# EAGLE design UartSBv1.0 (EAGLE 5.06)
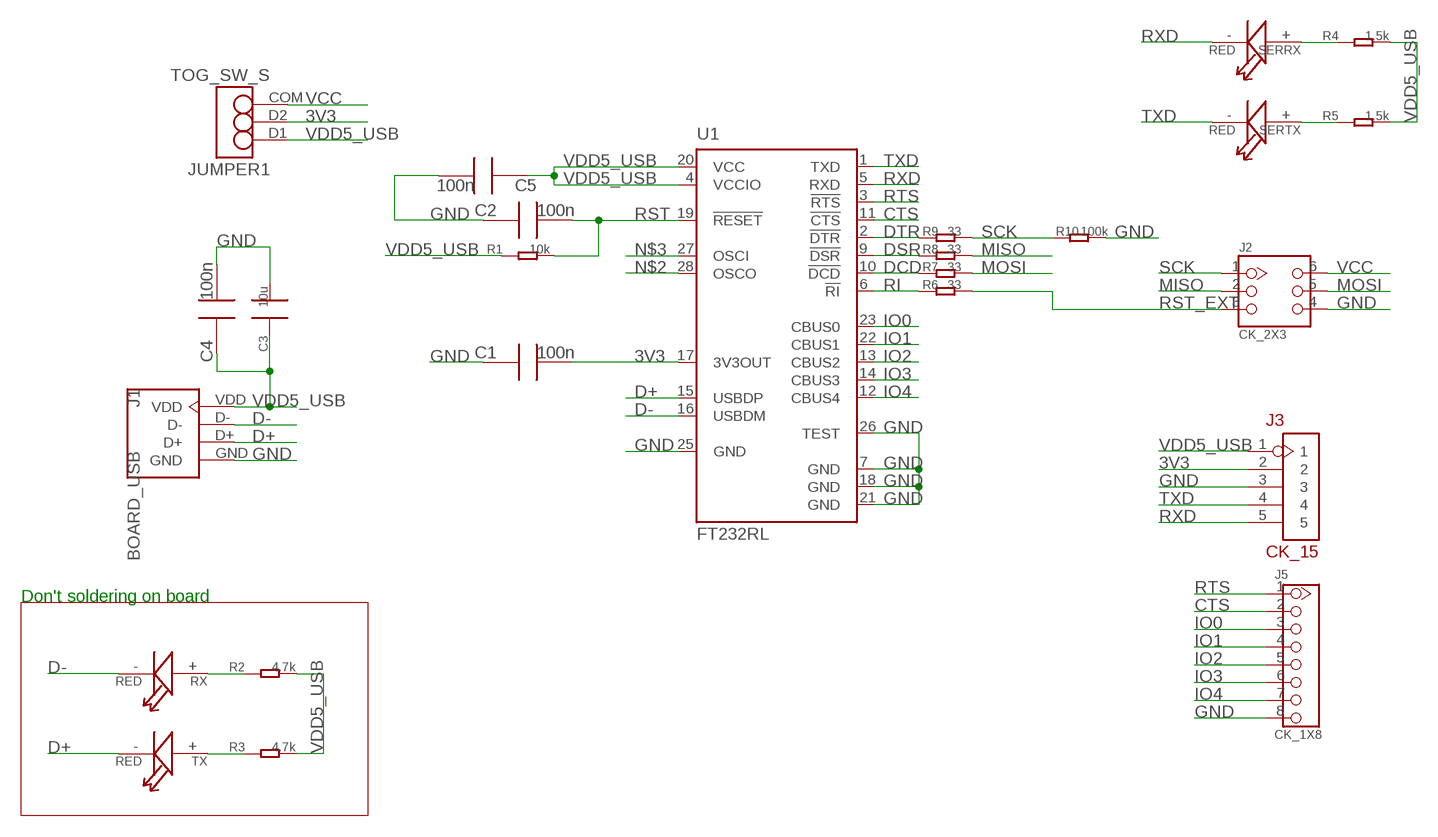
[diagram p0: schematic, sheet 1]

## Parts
C1  100n  C0603  [0603]
C2  100n  C0603  [0603]
C3  10u  C0805  [0805]
C4  100n  C0603  [0603]
C5  100n  C0603  [0603]
J1  BOARD_USB  [BOARD_USB]
J2  CK_2X3  [CK_2X3]
J3  CK_15  [CK_1*5]
J5  CK_1X8  [CK_1X8]
JUMPER1  TOG_SW_S  [TOG_SW_S]
R1  10k  R0603  [0603]
R2  4.7k  R0603  [0603]
R3  4.7k  R0603  [0603]
R4  1.5k  R0603  [0603]
R5  1.5k  R0603  [0603]
R6  33  R0603  [0603]
R7  33  R0603  [0603]
R8  33  R0603  [0603]
R9  33  R0603  [0603]
R10  100k  R0603  [0603]
RX  RED  LED0805  [LED0805]
SERRX  RED  LED0805  [LED0805]
SERTX  RED  LED0805  [LED0805]
TX  RED  LED0805  [LED0805]
U1  FT232RL  [SSOP28]

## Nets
3V3: C1.2 J3.2 JUMPER1.D2 U1.17(3V3OUT)
CTS: J5.2 U1.11(!CTS)
D+: J1.D+ TX.- U1.15(USBDP)
D-: J1.D- RX.- U1.16(USBDM)
DCD: R7.1 U1.10(!DCD)
DSR: R8.1 U1.9(!DSR)
DTR: R9.1 U1.2(!DTR)
GND: C1.1 C2.1 C3.2 C4.2 C5.2 J1.GND J2.4 J3.3 J5.8 R10.2 U1.7(GND) U1.18(GND) U1.21(GND) U1.25(GND) U1.26(TEST)
IO0: J5.3 U1.23(CBUS0)
IO1: J5.4 U1.22(CBUS1)
IO2: J5.5 U1.13(CBUS2)
IO3: J5.6 U1.14(CBUS3)
IO4: J5.7 U1.12(CBUS4)
MISO: J2.2 R8.2
MOSI: J2.5 R7.2
N$1: R4.1 SERRX.+
N$2: U1.28(OSCO)
N$3: U1.27(OSCI)
N$4: R5.1 SERTX.+
N$5: R2.1 RX.+
N$6: R3.1 TX.+
RI: R6.1 U1.6(!RI)
RST: C2.2 R1.2 U1.19(!RESET)
RST_EXT: J2.3 R6.2
RTS: J5.1 U1.3(!RTS)
RXD: J3.5 SERRX.- U1.5(RXD)
SCK: J2.1 R9.2 R10.1
TXD: J3.4 SERTX.- U1.1(TXD)
VCC: J2.6 JUMPER1.COM
VDD5_USB: C3.1 C4.1 C5.1 J1.VDD J3.1 JUMPER1.D1 R1.1 R2.2 R3.2 R4.2 R5.2 U1.4(VCCIO) U1.20(VCC)

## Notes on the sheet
- Don't soldering on board

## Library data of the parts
C1 C2 C4 C5 = CPT_SMD:C0603; C0603: 100N
C3 = CPT_SMD:C0805
J1 = CONNECTER:BOARD_USB
J2 = CONNECTER:CK_2X3
J3 = CONNECTER:CK_1*5
J5 = CONNECTER:CK_1X8
JUMPER1 = CPT_SMD:TOG_SW_S
R1-R10 = CPT_SMD:R0603
RX SERRX SERTX TX = CPT_SMD:LED0805
U1 = IC_SMD:FT232R: Source: http://www.ftdichip.com/Documents/DataSheets/DS_FT232R_v104.pdf

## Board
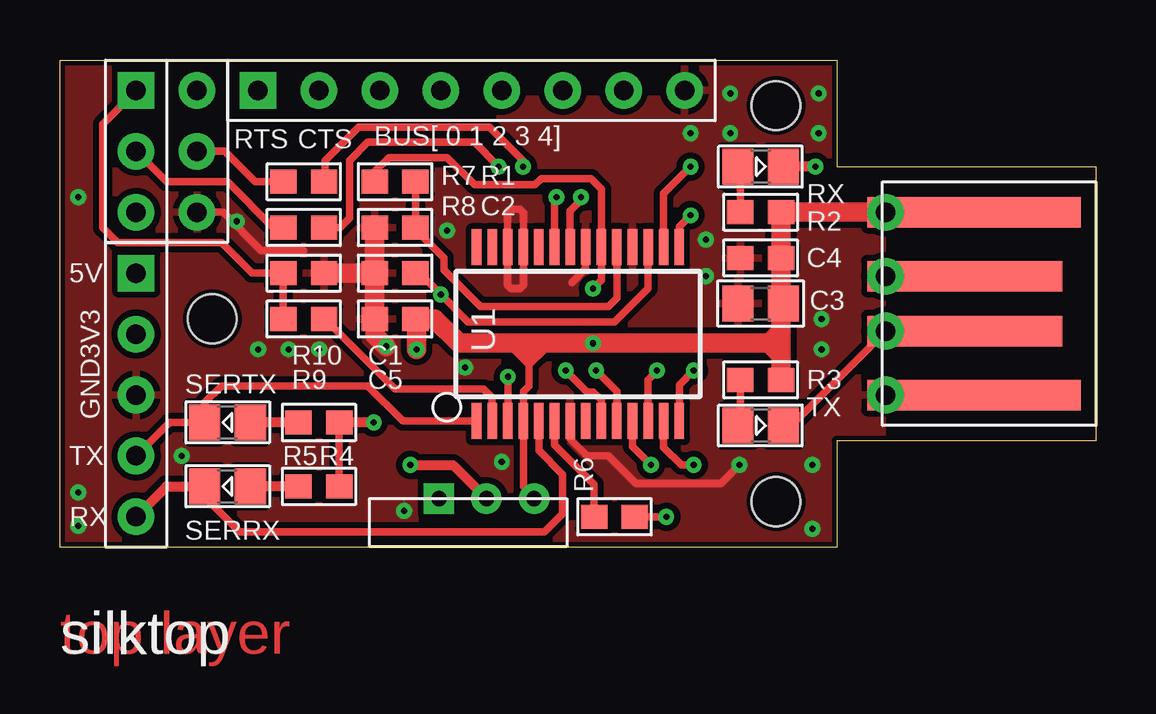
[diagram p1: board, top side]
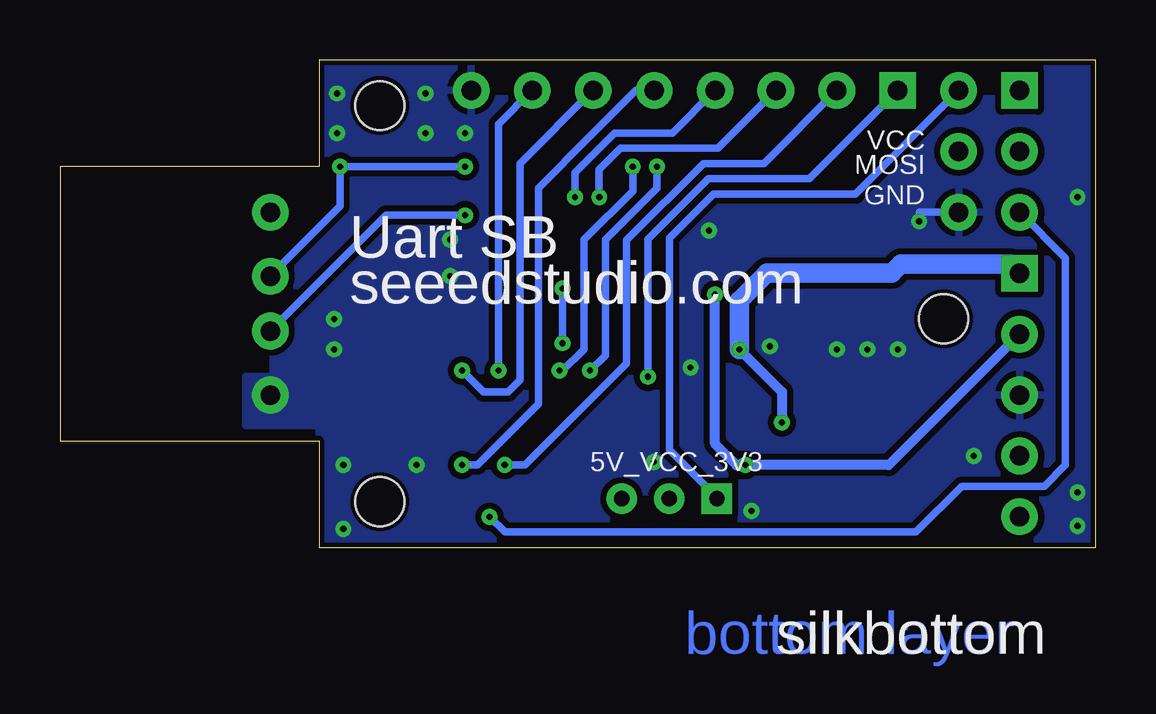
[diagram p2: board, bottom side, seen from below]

Size 43.18 x 20.32 mm. Coordinates in mm from the lower left corner, seen from the top.
Outline: 43.18,4.45 32.38,4.45 32.38,0 0,0 0,20.32 32.38,20.32 32.38,15.88 43.18,15.88 43.18,4.45
Copper layers (1*16): Top 0.035mm / dielectric 1.5mm / Bottom 0.035mm
Design rules "my rule": minimum track width 8mil, minimum drill 10mil, track to track 10mil, track to pad 6mil, pad to pad 6mil, via to via 10mil, smd to smd 6mil, copper to edge 5mil, drill to drill 10mil, minimum pad ring 10mil, minimum via ring 8mil, stop-mask expansion 3mil, vias tented up to drill 20mil, thermal gap 10mil
Holes 2.03 mm at 6.35,9.53 29.84,1.91 29.84,18.41
tRestrict: area 18.7,11.9 to 19.3,13; area 3.2,19.1 to 25.3,19.8; area 21,4.6 to 21.6,5.2
bRestrict: area 3.2,19.1 to 25.3,19.8

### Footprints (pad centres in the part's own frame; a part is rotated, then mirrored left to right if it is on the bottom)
0603 = smd 1.1 x 1: 1 -0.85,0; 2 0.85,0
0805 = smd 1.3 x 1.5: 1 -0.95,0; 2 0.95,0
BOARD_USB = smd 1.27 x 8.128: D+ 1.143,-0.381; D- -1.143,-0.381 | smd 1.27 x 8.89: GND 3.81,0; VDD -3.81,0
CK_2X3 = drill 0.813 pad 1.524 square: 1 -1.27,2.54 | drill 0.813 pad 1.524 round: 2 -1.27,0; 3 -1.27,-2.54; 4 1.27,-2.54; 5 1.27,0; 6 1.27,2.54
CK_1*5 = drill 0.813 pad 1.524 square: 1 0,5.08 | drill 0.813 pad 1.524 round: 2 0,2.54; 3 0,0; 4 0,-2.54; 5 0,-5.08
CK_1X8 = drill 0.813 pad 1.524 square: 1 0,8.89 | drill 0.813 pad 1.524 round: 2 0,6.35; 3 0,3.81; 4 0,1.27; 5 0,-1.27; 6 0,-3.81; 7 0,-6.35; 8 0,-8.89
TOG_SW_S = drill 0.635 pad 1.27 square: COM 0,-1.981 | drill 0.635 pad 1.27 round: D1 0,1.981; D2 0,0
LED0805 = smd 1.3 x 1.5: + -0.95,0; - 0.95,0
SSOP28 = smd 0.4 x 1.5: 1 -4.225,-3.625; 2 -3.575,-3.625; 3 -2.925,-3.625; 4 -2.275,-3.625; 5 -1.625,-3.625; 6 -0.975,-3.625; 7 -0.325,-3.625; 8 0.325,-3.625; 9 0.975,-3.625; 10 1.625,-3.625; 11 2.275,-3.625; 12 2.925,-3.625; 13 3.575,-3.625; 14 4.225,-3.625; 15 4.225,3.625; 16 3.575,3.625; 17 2.925,3.625; 18 2.275,3.625; 19 1.625,3.625; 20 0.975,3.625; 21 0.325,3.625; 22 -0.325,3.625; 23 -0.975,3.625; 24 -1.625,3.625; 25 -2.275,3.625; 26 -2.925,3.625; 27 -3.575,3.625; 28 -4.225,3.625

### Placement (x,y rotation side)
C1  13.97,11.43 0 top
C2  13.97,13.34 0 top
C3  29.21,10.16 180 top
C4  29.21,12.06 180 top
C5  13.97,9.53 180 top
J1  38.1,10.16 270 top
J2  4.45,16.51 0 top
J3  3.17,6.35 0 top
J5  17.14,19.05 90 top
JUMPER1  17.78,2.03 270 top
R1  13.97,15.24 0 top
R2  29.21,13.97 0 top
R3  29.21,6.99 0 top
R4  10.79,2.54 0 top
R5  10.79,5.21 0 top
R6  23.11,1.27 0 top
R7  10.16,15.24 180 top
R8  10.16,13.34 180 top
R9  10.16,9.53 180 top
R10  10.16,11.43 0 top
RX  29.21,15.88 0 top
SERRX  6.99,2.54 180 top
SERTX  6.99,5.21 180 top
TX  29.21,5.08 0 top
U1  21.59,8.89 0 top

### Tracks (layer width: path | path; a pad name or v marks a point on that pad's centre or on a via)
3V3  (via drill 0.25 pad 0.25)
  Top 0.305: C1.2 14.99,11.43 v15.88,10.54 17.02,9.4 23.11,9.4 24.52,10.8 U1.17
  Top 0.406: v14.61,3.43 16.38,3.43 JUMPER1.D2
  Bottom 0.406: v15.88,10.54 15.88,4.32 14.99,3.43 v14.61,3.43 8.64,3.43 J3.2
CTS  (via drill 0.25 pad 0.25)
  Top 0.305: U1.11 23.86,4.2 v24.64,3.43
  Bottom 0.305: J5.2 13.84,16 16.36,16 19.56,12.8 19.56,7.67 23.8,3.43 v24.64,3.43
D+  (via drill 0.25 pad 0.25, 0.81 pad 1.52)
  Top 0.305: U1.15 25.82,13.37 v26.29,13.84 | TX.- 30.48,5.08 v34.42,9.02
  Top 0.406: v34.42,9.02 J1.D+
  Bottom 0.305: v26.29,13.84 29.59,13.84 v34.42,9.02
D-  (via drill 0.25 pad 0.25, 0.81 pad 1.52)
  Top 0.305: U1.16 25.16,14.75 v26.29,15.88
  Top 0.406: v34.42,11.3 J1.D- | v31.5,15.88 RX.-
  Bottom 0.305: v26.29,15.88 v31.5,15.88 31.5,14.22 v34.42,11.3
DCD  (via drill 0.25 pad 0.25)
  Top 0.305: R7.1 11.05,15.24 11.05,16.13 12.45,17.53 17.91,17.53 19.3,16.13 v19.3,15.88 | U1.10 23.21,6.5 v22.35,7.37
  Bottom 0.305: v19.3,15.88 19.3,14.86 21.34,12.83 21.34,8.26 22.23,7.37 v22.35,7.37
DSR  (via drill 0.25 pad 0.25)
  Top 0.305: U1.9 22.57,6.14 22.23,6.48 21.97,6.48 v21.08,7.37 | R8.1 11.68,13.34 12.06,13.72 12.06,16.13 12.83,16.89 17.27,16.89 v18.29,15.88
  Bottom 0.305: v18.29,15.88 18.29,14.99 20.45,12.83 20.45,8 v21.08,7.37
DTR
  Top 0.305: 11.05,9.53 11.05,9.52 | U1.2 18.02,6.24 17.65,6.6 13.97,6.6 11.05,9.53 | R9.1 11.05,9.53
GND  (via drill 0.25 pad 0.25, 0.81 pad 1.52)
  Top 0.305: C2.1 13.08,13.34 13.12,13.3 | R10.2 11.01,11.53 | 10.16,12.38 8.38,12.38 6.79,13.97 J2.4 | U1.21 21.91,11.63 21.34,11.05 | U1.7 21.27,4.52 21.97,3.81 22.86,3.81 24,2.67 27.56,2.67 v28.32,3.43 | 19.32,10.93 U1.25 19.32,13.96 19.18,14.1 18.8,14.1 18.66,13.97 U1.26 18.66,10.93 18.8,10.79 19.18,10.79 19.32,10.93
  Top 0.406: v34.42,6.35 J1.GND
  Top 0.813: C1.1 13.14,11.43 | C1.1 R10.2 | C2.1 13.12,13.3 13.14,13.27 13.12,13.25 C1.1 | C5.2 13.14,9.53 | C1.1 13.12,9.55 13.14,9.53 | 13.14,9.53 13.14,8.83 v13.59,8.38
  Bottom 0.305: J2.4 7.37,13.97
  other vias: 31.75,8.26 31.75,9.53 26.29,17.27 26.92,12.83 26.92,11.3 16.89,7.49 16.13,13.21 27.94,17.27 27.94,18.92 31.62,18.92 31.62,17.27 31.37,3.43 10.79,8.26 9.53,8.26 8.26,8.26 5.08,3.81 31.37,0.76 14.35,1.52 7.37,13.59 0.76,14.61 0.76,0.89 0.76,2.29 18.41,3.56
  pour Bottom (isolate 0.203): 0,20.32 32.38,20.32 32.38,15.24 34.29,15.24 34.29,7.24 34.42,7.11 35.43,7.11 35.43,5.08 32.38,5.08 32.38,0 0,0
  pour Top (isolate 0.203): 0,20.32 32.38,20.32 32.38,15.24 34.29,15.24 34.29,4.7 32.38,4.7 32.38,0 0,0
IO0  (via drill 0.25 pad 0.25)
  Top 0.305: U1.23 20.61,14.52 v20.7,14.61
  Bottom 0.305: J5.3 15.75,16.64 19.81,16.64 20.7,15.75 v20.7,14.61
IO1  (via drill 0.25 pad 0.25)
  Top 0.305: v21.72,14.61 21.72,14.48 21.27,14.03 U1.22
  Bottom 0.305: J5.4 17.65,17.27 20.07,17.27 21.72,15.62 v21.72,14.61
IO2  (via drill 0.25 pad 0.25)
  Top 0.305: U1.13 25.16,4.17 25.91,3.43 v26.42,3.43
  Bottom 0.305: v26.42,3.43 25.78,3.43 23.24,5.97 23.24,14.98 21.08,17.14 19.18,19.05 J5.5
IO3  (via drill 0.25 pad 0.25)
  Top 0.305: U1.14 25.82,6.76 v26.42,7.37
  Bottom 0.305: J5.6 24,16 24,6.99 24.51,6.48 25.53,6.48 v26.42,7.37
IO4  (via drill 0.25 pad 0.25)
  Top 0.305: U1.12 24.51,6.99 v24.89,7.37
  Bottom 0.305: J5.7 24.89,17.65 v24.89,7.37
MISO
  Top 0.305: R8.2 8.89,13.34 6.99,15.24 4.45,15.24 J2.2
MOSI
  Top 0.305: J2.5 6.86,16.51 8.13,15.24 R7.2
N$1
  Top 0.406: R4.1 SERRX.+
N$4
  Top 0.406: R5.1 SERTX.+
N$5
  Top 0.305: RX.+ 28.32,15.88 28.36,15.84 R2.1
N$6
  Top 0.305: TX.+ 28.19,5.08 28.36,5.25 R3.1
RI
  Top 0.305: U1.6 20.61,4.28 22.26,2.63 R6.1
RST
  Top 0.305: R1.2 14.86,15.24 14.82,15.2 C2.2 | C2.2 15.11,13.34 | C2.2 14.82,13.25 16,12.06 16,11.56 17.53,10.03 22.86,10.03 23.21,10.39 U1.19
RST_EXT  (via drill 0.25 pad 0.25)
  Top 0.305: v25.27,1.27 R6.2
  Bottom 0.305: J2.3 1.27,12.06 1.27,3.43 2.16,2.54 5.59,2.54 7.49,0.64 24.64,0.64 v25.27,1.27
RTS  (via drill 0.25 pad 0.25)
  Top 0.305: U1.3 18.66,5.21 18.67,5.21 v18.67,7.11
  Bottom 0.305: J5.1 11.94,15.37 16.15,15.37 18.67,12.85 v18.67,7.11
RXD
  Top 0.305: U1.5 19.96,4.04 20.95,3.05 20.95,1.4 20.19,0.64 7.49,0.64 6.1,2.03 6.1,2.41 | 5.97,2.54 SERRX.-
  Top 0.406: 6.1,2.41 5.97,2.54 4.45,2.54 J3.5
SCK
  Top 0.305: R9.2 9.27,9.53 9.31,9.56 R10.1 8,11.43 6.73,12.7 2.41,12.7 1.78,13.34 1.78,17.65 J2.1
TXD
  Top 0.305: U1.1 14.29,5.26 12.83,6.73 6.73,6.73 6.04,6.04 SERTX.- 4.57,5.21 J3.4
VCC
  Bottom 0.305: J2.6 10.03,14.73 15.95,14.73 17.78,12.9 17.78,4.06 15.8,2.08 JUMPER1.COM
VDD5_USB  (via drill 0.25 pad 0.25, 0.81 pad 1.52)
  Top 0.305: C4.1 30.1,12.06 30.06,12.1 | 30.06,10.2 30.1,10.16 C3.1 30.23,10.16 30.06,9.99 | 30.06,9.02 29.72,9.02 29.21,8.51 29.84,7.87 29.84,8.89 29.46,8.51 29.46,8.26 29.72,8.51 29.84,8.51 | JUMPER1.D1 19.76,2.08 19.32,2.53 U1.4 19.32,6.49 19.56,6.73 19.56,7.62 | 14.86,9.53 C5.1 | 19.56,7.62 19.56,8.51 | 19.56,7.87 18.92,8.51 18.92,8.26 19.56,7.62 | 20.19,8.51 20.19,8.26 19.56,7.62 | 19.56,7.87 19.56,7.62 | 20.19,8.51 19.56,7.87 | 20.45,8.51 20.19,8.51 | R1.1 13.12,15.66 13.72,16.26 16.13,16.26 17.27,15.11 19.81,15.11 20.07,15.37 22.14,15.37 22.57,14.94 U1.20 22.57,11.13 v22.23,10.79 | R4.2 11.64,5.17 11.68,5.21
  Top 0.406: v34.42,13.97 J1.VDD | v13.08,5.21 11.68,5.21 R5.2
  Top 0.813: v34.42,13.97 R2.2 30.06,12.1 | 30.06,10.2 C4.1 | R3.2 30.06,9.02 30.06,9.99 | 29.72,8.51 29.21,8.51 v22.23,8.51 20.45,8.51 16.64,8.51 15.62,9.53 14.86,9.53 v14.86,8.26
  Bottom 0.305: v22.23,8.51 v22.23,10.79
  Bottom 0.406: v13.08,5.21 13.08,6.48 v14.86,8.26
  Bottom 0.813: v14.86,8.26 14.86,10.29 13.72,11.43 8.51,11.43 8.13,11.81 3.56,11.81 J3.1

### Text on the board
Top: top layer
Bottom: bottom layer
tPlace: RTS | CTS | BUS[ 0 1 2 3 4] | 5V | 3V3 | GND | TX | RX | silktop
bPlace: VCC | MOSI | GND | Uart SB | seeedstudio.com | 5V_VCC_3V3 | silkbottom
tStop: soldermask top
bStop: soldermask bottom
Drill_legend: Drill legend | Date: 2008-10-16 09:38:00 ÉÏÎç | 2.0320 mm / 80.000 mil | 0.8128 mm / 32.000 mil | 0.6350 mm / 25.000 mil | 0.2540 mm / 10.000 mil | board thickness:1.6mm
